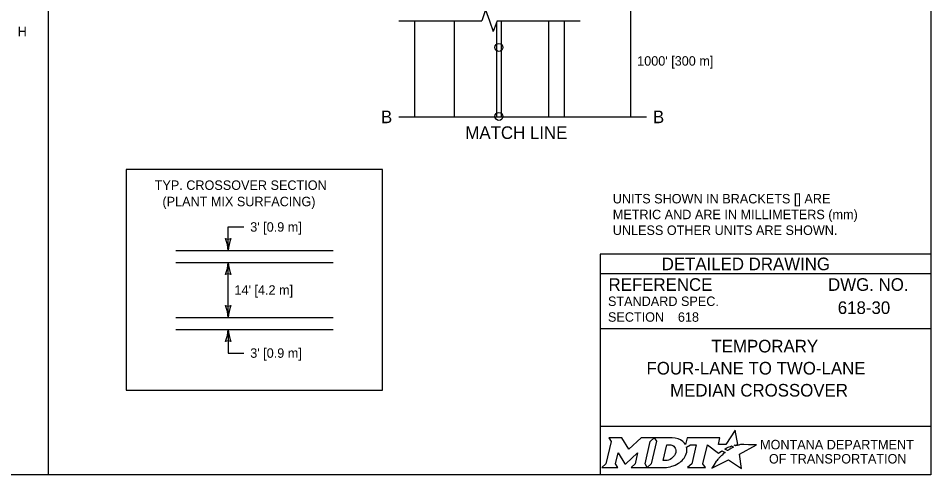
# Model space of a CAD drawing. Extents: x 49991.4 to 50021, y 49987.6 to 50011.4.
# Drawn here: x 50010.96 to 50016.75, y 49987.8 to 49990.69 of the extents above; entities that cross this region are included whole.
import ezdxf

# ---------------------------------------------------------------- set-up
doc = ezdxf.new("R2010")
doc.units = 0
for name, color, linetype in [('Default', 7, 'Continuous'), ('Level 1', 7, 'Continuous'), ('Level 2', 7, 'Continuous'), ('Level 3', 7, 'Continuous'), ('Level 5', 7, 'Continuous'), ('Level 6', 7, 'Continuous')]:
    doc.layers.add(name, color=color, linetype=linetype)

msp = doc.modelspace()

# ---------------------------------------------------------------- linework, layer by layer
at = {"layer": 'Default'}
for points in [[(50015.5126, 49987.9811), (50015.5023, 49987.9867), (50015.5139, 49987.9895), (50015.5255, 49987.9915), (50015.5081, 49988.0816), (50015.4486, 49987.9903), (50015.4013, 49987.9896), (50015.4116, 49988.0337), (50015.2024, 49988.0338), (50015.1923, 49987.9913), (50015.1865, 49987.9996)], [(50014.7056, 49988.0338), (50014.7197, 49988.0104), (50014.6862, 49987.8671), (50014.6605, 49987.8446), (50014.7621, 49987.8446), (50014.7486, 49987.8674), (50014.7648, 49987.9375), (50014.8085, 49987.8685), (50014.8138, 49987.8685), (50014.8889, 49987.938), (50014.8725, 49987.8669), (50014.8478, 49987.8449), (50014.9494, 49987.8449), (50014.9356, 49987.8682), (50014.9688, 49988.0106)], [(50014.9688, 49988.0106), (50014.9941, 49988.0338), (50014.9117, 49988.0338), (50014.8321, 49987.9608), (50014.7876, 49988.0335), (50014.7056, 49988.0338)], [(50015.1077, 49988.0338), (50014.9941, 49988.0338), (50015.0088, 49988.0109), (50014.9749, 49987.8671), (50014.9494, 49987.8449), (50015.06, 49987.8449)], [(50015.1317, 49987.9471), (50015.1305, 49987.939), (50015.1273, 49987.9297), (50015.1231, 49987.9215), (50015.1175, 49987.914), (50015.111, 49987.9071), (50015.1031, 49987.9008), (50015.0948, 49987.8961), (50015.0857, 49987.8922), (50015.0766, 49987.8899), (50015.0674, 49987.889), (50015.0515, 49987.889), (50015.0751, 49987.989), (50015.0911, 49987.989), (50015.0987, 49987.9884), (50015.1063, 49987.9865), (50015.1129, 49987.9835), (50015.119, 49987.9793), (50015.1238, 49987.9743), (50015.1275, 49987.9683), (50015.1302, 49987.9621), (50015.1318, 49987.9547), (50015.1318, 49987.9517), (50015.1317, 49987.9471)], [(50015.1991, 49987.9747), (50015.2237, 49987.9878), (50015.2606, 49987.9878), (50015.232, 49987.8673), (50015.2045, 49987.8446), (50015.3207, 49987.8446), (50015.3037, 49987.8675), (50015.3319, 49987.9877), (50015.4032, 49987.936), (50015.4243, 49987.9511), (50015.444, 49987.9402)], [(50015.3882, 49987.8843), (50015.3729, 49987.8599), (50015.3682, 49987.8524), (50015.3624, 49987.8438), (50015.3601, 49987.8395), (50015.4654, 49987.8926), (50015.5493, 49987.8375), (50015.5362, 49987.9302), (50015.6431, 49987.9886), (50015.5938, 49987.9894), (50015.5637, 49987.9898), (50015.5429, 49987.9901), (50015.5361, 49987.9886), (50015.5312, 49987.9874), (50015.5228, 49987.9851), (50015.5126, 49987.9811)], [(50015.4622, 49987.9535), (50015.4598, 49987.9518), (50015.4415, 49987.9614), (50015.4518, 49987.9671), (50015.4559, 49987.9693), (50015.4645, 49987.9733), (50015.4702, 49987.9759), (50015.4781, 49987.9789), (50015.4854, 49987.9816), (50015.4972, 49987.9742), (50015.4932, 49987.9721), (50015.4886, 49987.9696), (50015.4844, 49987.9674), (50015.4794, 49987.9645), (50015.4775, 49987.9634), (50015.4748, 49987.9618), (50015.4723, 49987.9604), (50015.47, 49987.9588), (50015.4674, 49987.957), (50015.4647, 49987.9552), (50015.4622, 49987.9535)], [(50015.4021, 49987.9004), (50015.4021, 49987.9004)], [(50015.1057, 49987.8522), (50015.1141, 49987.8548), (50015.1271, 49987.8602), (50015.1475, 49987.8712)]]:
    msp.add_lwpolyline(points, dxfattribs=at)
for centre, radius, start, end in [((50015.1308, 49987.9554), 0.0709, 339.53292, 15.85821), ((50015.0868, 49987.9727), 0.1183, 300.91025, 339.13831)]:
    msp.add_arc(centre, radius, start, end, dxfattribs=at)
for centre, major_axis, ratio, start_param, end_param in [((50015.1056, 49987.9864), (0.0834, -0.0037), 0.568097, 0.61298, 1.570796), ((50015.1612, 49987.9937), (0.0361, -0.0295), 0.469099, 1.225588, 1.570796), ((50015.3952, 49987.8923), (-0.00694, -0.00806), 0.008222, 0, 3.137361), ((50015.4119, 49987.9106), (-0.0098, -0.0102), 0.016458, 3.141593, 6.279097), ((50015.4329, 49987.9305), (-0.0112, -0.0097), 0.021651, 3.157348, 6.283185), ((50015.0603, 49987.9932), (0, 0.1484), 0.987302, 3.139398, 3.456847)]:
    msp.add_ellipse(centre, major_axis=major_axis, ratio=ratio, start_param=start_param, end_param=end_param, dxfattribs=at)
at = {"layer": 'Level 1'}
for p, q in [((50013.4728, 49990.679), (50013.4728, 49990.069)), ((50013.7228, 49990.679), (50013.7228, 49990.069)), ((50014.0228, 49990.679), (50014.0228, 49990.069)), ((50014.3228, 49990.679), (50014.3228, 49990.069)), ((50014.4228, 49990.679), (50014.4228, 49990.069)), ((50013.9928, 49990.6689), (50013.9928, 49990.069)), ((50011.9554, 49989.2207), (50012.9554, 49989.2207)), ((50011.9554, 49989.1457), (50012.9554, 49989.1457)), ((50011.9554, 49988.7957), (50012.9554, 49988.7957)), ((50011.9554, 49988.7207), (50012.9554, 49988.7207))]:
    msp.add_line(p, q, dxfattribs=at)
msp.add_lwpolyline([(49999.3835, 49998.9992), (50016.7501, 49998.9992), (50016.7501, 49987.7988), (49999.3835, 49987.7988)], close=True, dxfattribs=at)
for centre in [(50014.0079, 49990.5095), (50014.0079, 49990.072)]:
    msp.add_circle(centre, 0.025, dxfattribs=at)
at = {"layer": 'Level 2'}
msp.add_lwpolyline([(50011.6418, 49988.3357), (50013.2691, 49988.3357), (50013.2691, 49989.7357), (50011.6418, 49989.7357)], close=True, dxfattribs=at)
at = {"layer": 'Level 3'}
for p, q in [((50011.1455, 49998.9992), (50011.1455, 49987.7988)), ((50014.8458, 49990.069), (50014.8458, 49990.779)), ((50012.2887, 49989.2207), (50012.2887, 49989.3707)), ((50012.2887, 49989.3707), (50012.3887, 49989.3707)), ((50012.2887, 49988.7957), (50012.2887, 49989.1457)), ((50012.2887, 49988.7207), (50012.2887, 49988.5707)), ((50012.2887, 49988.5707), (50012.3887, 49988.5707))]:
    msp.add_line(p, q, dxfattribs=at)
for centre, radius, start, end in [((50012.2887, 49989.3489), 0.0548, 252.13882, 287.86118), ((50012.056, 49989.2092), 0.233, 2.82731, 22.07716), ((50012.5109, 49989.2115), 0.2223, 157.45601, 177.63952), ((50012.0666, 49989.1548), 0.2223, 337.45601, 357.63952), ((50012.5214, 49989.1572), 0.233, 182.82731, 202.07716), ((50012.2887, 49989.0175), 0.0548, 72.13882, 107.86118), ((50012.2887, 49988.9239), 0.0548, 252.13882, 287.86118), ((50012.056, 49988.7842), 0.233, 2.82731, 22.07716), ((50012.5109, 49988.7865), 0.2223, 157.45601, 177.63952), ((50012.0666, 49988.7298), 0.2223, 337.45601, 357.63952), ((50012.5214, 49988.7322), 0.233, 182.82731, 202.07716), ((50012.2887, 49988.5925), 0.0548, 72.13882, 107.86118)]:
    msp.add_arc(centre, radius, start, end, dxfattribs=at)
at = {"layer": 'Level 5'}
for p, q in [((50016.7501, 49989.1988), (50014.6501, 49989.1988)), ((50014.6501, 49989.1988), (50014.6501, 49987.7988)), ((50016.7501, 49989.0738), (50014.6501, 49989.0738)), ((50016.3862, 49988.8587), (50016.3862, 49988.8587)), ((50015.1444, 49988.7993), (50015.1444, 49988.7993)), ((50016.7501, 49988.7238), (50014.6501, 49988.7238)), ((50015.7001, 49988.4747), (50015.7001, 49988.4747)), ((50016.7501, 49988.1057), (50014.6501, 49988.1057))]:
    msp.add_line(p, q, dxfattribs=at)
at = {"layer": 'Level 6'}
for p, q in [((50013.9236, 49990.7474), (50013.8992, 49990.679)), ((50013.9236, 49990.7474), (50013.9478, 49990.679)), ((50013.3728, 49990.679), (50013.8992, 49990.679)), ((50013.9478, 49990.679), (50013.972, 49990.6102)), ((50013.9964, 49990.679), (50013.972, 49990.6102)), ((50013.9964, 49990.679), (50014.5228, 49990.679)), ((50013.3728, 49990.069), (50014.9458, 49990.069))]:
    msp.add_line(p, q, dxfattribs=at)

# ---------------------------------------------------------------- texts
at = {"layer": 'Default'}
for s, p in [('MONTANA DEPARTMENT', (50015.6663, 49987.96)), ('OF TRANSPORTATION', (50015.7225, 49987.87))]:
    msp.add_text(s, height=0.06, dxfattribs=at).set_placement(p)
at = {"layer": 'Level 2'}
for s, height, p in [('H', 0.06, (50010.9522, 49990.5804)), ("1000' [300 m]", 0.06, (50014.8858, 49990.394)), ('B', 0.08, (50013.2588, 49990.029)), ('B', 0.08, (50014.9858, 49990.029)), ('MATCH LINE', 0.08, (50013.7947, 49989.929)), ('TYP. CROSSOVER SECTION', 0.06, (50011.822, 49989.6059)), ('UNITS SHOWN IN BRACKETS [] ARE ', 0.06, (50014.7309, 49989.52)), ('(PLANT MIX SURFACING)', 0.06, (50011.8712, 49989.5022)), ('METRIC AND ARE IN MILLIMETERS (mm) ', 0.06, (50014.7309, 49989.42)), ("3' [0.9 m]", 0.06, (50012.4287, 49989.3407)), ('UNLESS OTHER UNITS ARE SHOWN.', 0.06, (50014.7309, 49989.32)), ("14' [4.2 m]", 0.06, (50012.3287, 49988.9407)), ('618-30', 0.08, (50016.1596, 49988.8187)), ('618', 0.06, (50015.1444, 49988.7693)), ('TEMPORARY', 0.08, (50015.3574, 49988.5747)), ("3' [0.9 m]", 0.06, (50012.4287, 49988.5407)), ('FOUR-LANE TO TWO-LANE', 0.08, (50014.9451, 49988.4347)), ('MEDIAN CROSSOVER', 0.08, (50015.0949, 49988.2947))]:
    msp.add_text(s, height=height, dxfattribs=at).set_placement(p)
at = {"layer": 'Level 5'}
for s, height, p in [('DETAILED DRAWING', 0.0799, (50015.0418, 49989.0963)), ('REFERENCE', 0.08, (50014.7037, 49988.9654)), ('DWG. NO.', 0.08, (50016.0979, 49988.9654)), ('STANDARD SPEC.', 0.06, (50014.7004, 49988.8694)), ('SECTION', 0.06, (50014.7004, 49988.7694))]:
    msp.add_text(s, height=height, dxfattribs=at).set_placement(p)

doc.saveas('drawing.dxf')
